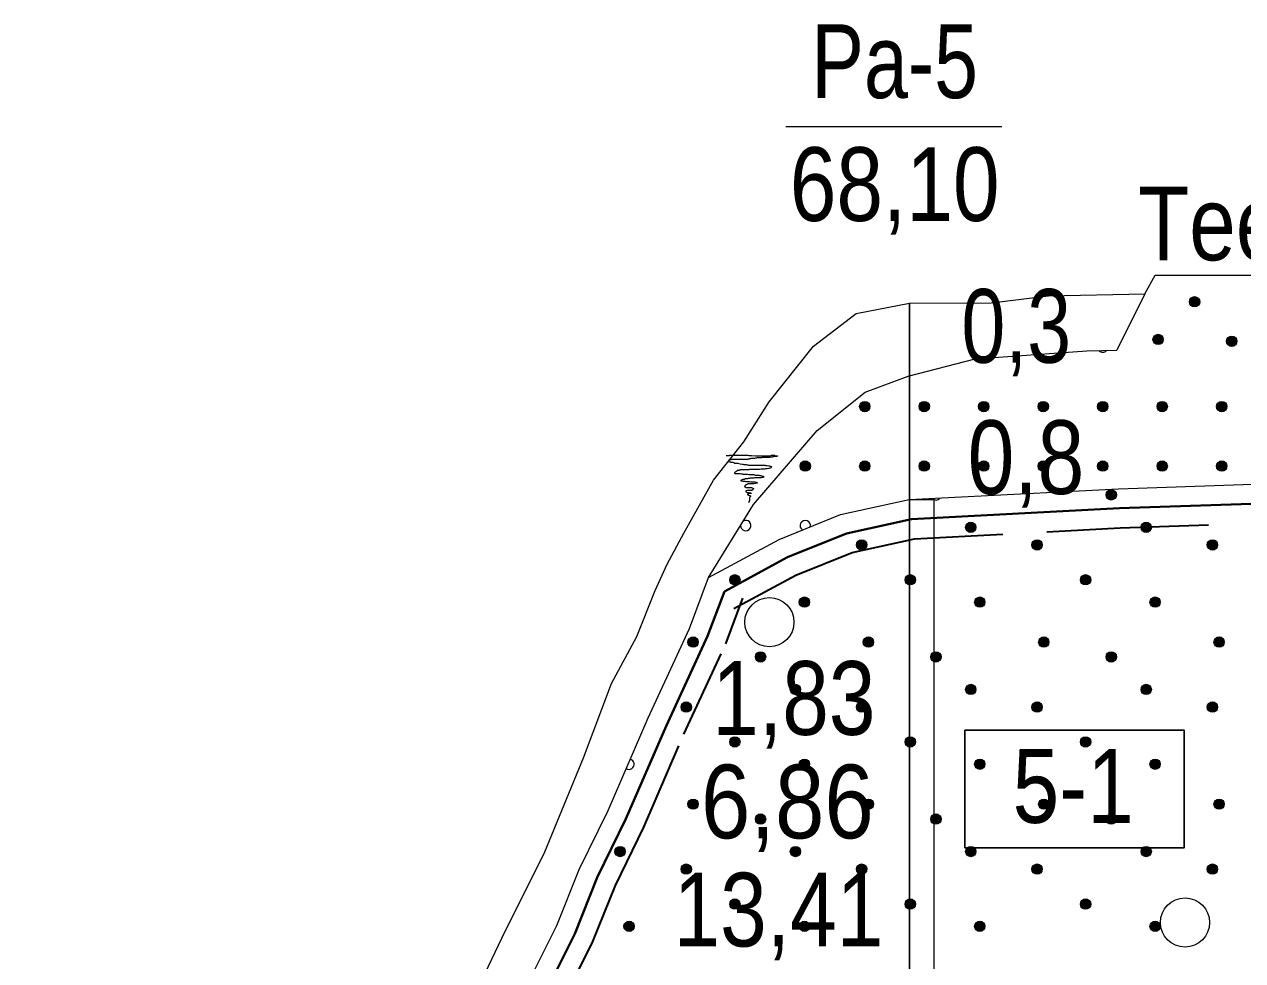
# Model space of a CAD drawing. Extents: x 640121 to 640955, y 6441885 to 6442246.
# Drawn here: x 640175.81 to 640225.36, y 6441992.66 to 6442030.76 of the extents above; entities that cross this region are included whole.
import ezdxf
from ezdxf.enums import TextEntityAlignment as Align

# ---------------------------------------------------------------- set-up
doc = ezdxf.new("R2010")
doc.units = 0
doc.header["$LTSCALE"] = 1.2
doc.linetypes.add('MEDIUM_DASHED', pattern=[4.5, 3, -1.5])
for name, color, linetype, lineweight in [('31', 7, 'Continuous', 13), ('32', 7, 'Continuous', 13), ('33', 7, 'Continuous', 13), ('35', 7, 'Continuous', 35), ('40', 7, 'Continuous', 13), ('44', 7, 'Continuous', 13), ('45', 7, 'Continuous', 13), ('47', 7, 'Continuous', 13)]:
    doc.layers.add(name, color=color, linetype=linetype, lineweight=lineweight)

msp = doc.modelspace()

# ---------------------------------------------------------------- hatches: boundary and pattern name
at = {"layer": '44'}
for points in [[(640220.231, 6442011.616, 1), (640219.811, 6442011.616, 1)], [(640214.517, 6442010.294, 1), (640214.097, 6442010.294, 1)], [(640221.65, 6442010.294, 1), (640221.23, 6442010.294, 1)], [(640210.077, 6442009.578, 1), (640209.657, 6442009.578, 1)], [(640217.21, 6442009.578, 1), (640216.79, 6442009.578, 1)], [(640224.343, 6442009.578, 1), (640223.923, 6442009.578, 1)], [(640204.921, 6442008.159, 1), (640204.501, 6442008.159, 1)], [(640212.054, 6442008.159, 1), (640211.634, 6442008.159, 1)], [(640219.187, 6442008.159, 1), (640218.767, 6442008.159, 1)], [(640207.748, 6442007.251, 1), (640207.328, 6442007.251, 1)], [(640214.881, 6442007.251, 1), (640214.461, 6442007.251, 1)], [(640222.014, 6442007.251, 1), (640221.594, 6442007.251, 1)], [(640203.218, 6442005.626, 1), (640202.798, 6442005.626, 1)], [(640210.351, 6442005.626, 1), (640209.931, 6442005.626, 1)], [(640217.484, 6442005.626, 1), (640217.064, 6442005.626, 1)], [(640224.617, 6442005.626, 1), (640224.197, 6442005.626, 1)], [(640205.965, 6442005.02, 1), (640205.545, 6442005.02, 1)], [(640213.098, 6442005.02, 1), (640212.678, 6442005.02, 1)], [(640220.231, 6442005.02, 1), (640219.811, 6442005.02, 1)], [(640207.384, 6442003.698, 1), (640206.964, 6442003.698, 1)], [(640214.517, 6442003.698, 1), (640214.097, 6442003.698, 1)], [(640221.65, 6442003.698, 1), (640221.23, 6442003.698, 1)], [(640202.944, 6442002.982, 1), (640202.524, 6442002.982, 1)], [(640210.077, 6442002.982, 1), (640209.657, 6442002.982, 1)], [(640217.21, 6442002.982, 1), (640216.79, 6442002.982, 1)], [(640224.343, 6442002.982, 1), (640223.923, 6442002.982, 1)], [(640204.921, 6442001.563, 1), (640204.501, 6442001.563, 1)], [(640212.054, 6442001.563, 1), (640211.634, 6442001.563, 1)], [(640219.187, 6442001.563, 1), (640218.767, 6442001.563, 1)], [(640207.748, 6442000.655, 1), (640207.328, 6442000.655, 1)], [(640214.881, 6442000.655, 1), (640214.461, 6442000.655, 1)], [(640222.014, 6442000.655, 1), (640221.594, 6442000.655, 1)], [(640203.218, 6441999.03, 1), (640202.798, 6441999.03, 1)], [(640210.351, 6441999.03, 1), (640209.931, 6441999.03, 1)], [(640217.484, 6441999.03, 1), (640217.064, 6441999.03, 1)], [(640224.617, 6441999.03, 1), (640224.197, 6441999.03, 1)], [(640205.965, 6441998.424, 1), (640205.545, 6441998.424, 1)], [(640213.098, 6441998.424, 1), (640212.678, 6441998.424, 1)], [(640220.231, 6441998.424, 1), (640219.811, 6441998.424, 1)], [(640200.251, 6441997.102, 1), (640199.831, 6441997.102, 1)], [(640207.384, 6441997.102, 1), (640206.964, 6441997.102, 1)], [(640214.517, 6441997.102, 1), (640214.097, 6441997.102, 1)], [(640221.65, 6441997.102, 1), (640221.23, 6441997.102, 1)], [(640202.944, 6441996.386, 1), (640202.524, 6441996.386, 1)], [(640210.077, 6441996.386, 1), (640209.657, 6441996.386, 1)], [(640217.21, 6441996.386, 1), (640216.79, 6441996.386, 1)], [(640224.343, 6441996.386, 1), (640223.923, 6441996.386, 1)], [(640204.921, 6441994.967, 1), (640204.501, 6441994.967, 1)], [(640212.054, 6441994.967, 1), (640211.634, 6441994.967, 1)], [(640219.187, 6441994.967, 1), (640218.767, 6441994.967, 1)], [(640200.615, 6441994.059, 1), (640200.195, 6441994.059, 1)], [(640207.748, 6441994.059, 1), (640207.328, 6441994.059, 1)], [(640214.881, 6441994.059, 1), (640214.461, 6441994.059, 1)], [(640222.014, 6441994.059, 1), (640221.594, 6441994.059, 1)]]:
    msp.add_hatch(color=256, dxfattribs=at).paths.add_polyline_path(points)
at = {"layer": '45'}
for points in [[(640223.621, 6442019.471, 1), (640223.201, 6442019.471, 1)], [(640222.136, 6442017.938, 1), (640221.716, 6442017.938, 1)], [(640225.13, 6442017.866, 1), (640224.71, 6442017.866, 1)], [(640210.203, 6442015.207, 1), (640209.783, 6442015.207, 1)], [(640212.623, 6442015.207, 1), (640212.203, 6442015.207, 1)], [(640215.043, 6442015.207, 1), (640214.623, 6442015.207, 1)], [(640217.463, 6442015.207, 1), (640217.043, 6442015.207, 1)], [(640219.883, 6442015.207, 1), (640219.463, 6442015.207, 1)], [(640222.303, 6442015.207, 1), (640221.883, 6442015.207, 1)], [(640224.723, 6442015.207, 1), (640224.303, 6442015.207, 1)], [(640207.783, 6442012.787, 1), (640207.363, 6442012.787, 1)], [(640210.203, 6442012.787, 1), (640209.783, 6442012.787, 1)], [(640212.623, 6442012.787, 1), (640212.203, 6442012.787, 1)], [(640215.043, 6442012.787, 1), (640214.623, 6442012.787, 1)], [(640217.463, 6442012.787, 1), (640217.043, 6442012.787, 1)], [(640219.883, 6442012.787, 1), (640219.463, 6442012.787, 1)], [(640222.303, 6442012.787, 1), (640221.883, 6442012.787, 1)], [(640224.723, 6442012.787, 1), (640224.303, 6442012.787, 1)]]:
    msp.add_hatch(color=256, dxfattribs=at).paths.add_polyline_path(points)

# ---------------------------------------------------------------- linework, layer by layer
at = {"layer": '31'}
msp.add_line((640221.38, 6442019.79), (640220.24, 6442017.5), dxfattribs=at)
for points in [[(640192.4, 6441987.63), (640195.23, 6441993.58), (640196.98, 6441997.09), (640198.55, 6442000.91), (640199.69, 6442003.94), (640200.72, 6442005.85), (640201.47, 6442007.72), (640201.96, 6442008.8), (640202.64, 6442010.06), (640203.84, 6442012.22), (640205.08, 6442013.77), (640206.11, 6442015.4), (640207.91, 6442017.67), (640209.64, 6442018.99), (640211.81, 6442019.41), (640215.13, 6442019.43), (640217.47, 6442019.72), (640221.38, 6442019.79), (640221.81, 6442020.56), (640225.76, 6442020.56)], [(640196.56, 6441992.27), (640197.47, 6441994.09), (640198.38, 6441996.37), (640199.55, 6441998.77), (640201.18, 6442002.54), (640202.86, 6442006.18), (640203.64, 6442008.25), (640205.47, 6442011.23), (640208.06, 6442014.23), (640210.01, 6442015.79), (640211.76, 6442016.44), (640214.49, 6442017.15), (640219.03, 6442017.48), (640220.24, 6442017.5)], [(640203.64, 6442008.25), (640206.51, 6442009.8), (640209.01, 6442010.81), (640211.8, 6442011.42), (640220.31, 6442011.86), (640226.94, 6442012.09), (640231.69, 6442012.26), (640234.41, 6442012.07), (640236.57, 6442011.92), (640240.41, 6442011.03), (640242.19, 6442010.47)]]:
    msp.add_lwpolyline(points, dxfattribs=at)
at = {"layer": '32'}
msp.add_line((640206.78, 6442026.6), (640215.57, 6442026.6), dxfattribs=at)
at = {"layer": '32', "lineweight": 25}
msp.add_line((640211.81, 6442019.41), (640211.81, 6441914.41), dxfattribs=at)
at = {"layer": '33'}
msp.add_lwpolyline([(640212.81, 6441989.41), (640212.81, 6442011.41), (640211.81, 6442011.41), (640211.81, 6441989.41)], close=True, dxfattribs=at)
at = {"layer": '33', "lineweight": 25}
msp.add_lwpolyline([(640214.07, 6442002.04), (640222.99, 6442002.04), (640222.99, 6441997.26), (640214.07, 6441997.26)], close=True, dxfattribs=at)
at = {"layer": '35', "lineweight": 40}
for points in [[(640204.29, 6442007.69), (640206.85, 6442009.08), (640209.25, 6442010.04), (640211.9, 6442010.62), (640220.35, 6442011.07), (640226.96, 6442011.29), (640231.68, 6442011.46), (640234.36, 6442011.28), (640236.45, 6442011.13), (640240.2, 6442010.26), (640241.6, 6442009.82)], [(640175.81, 6441965.88), (640176.44, 6441966.07), (640179.09, 6441967.84), (640182.86, 6441971.46), (640184.6, 6441973.14), (640186.28, 6441975.02), (640188.99, 6441978.04), (640192.07, 6441982.34), (640194.62, 6441986.76), (640196.44, 6441989.9), (640197.29, 6441991.94), (640198.2, 6441993.76), (640199.11, 6441996.04), (640200.28, 6441998.44), (640201.91, 6442002.21), (640203.6, 6442005.87), (640204.29, 6442007.69)]]:
    msp.add_lwpolyline(points, dxfattribs=at)
at = {"layer": '35', "linetype": 'MEDIUM_DASHED'}
for points in [[(640204.67, 6442006.99), (640207.19, 6442008.35), (640209.48, 6442009.27), (640212.01, 6442009.83), (640220.38, 6442010.27), (640226.99, 6442010.49), (640231.66, 6442010.66), (640234.3, 6442010.48), (640236.33, 6442010.33), (640239.99, 6442009.48), (640241.36, 6442009.06)], [(640176.61, 6441965.22), (640179.6, 6441967.21), (640183.42, 6441970.88), (640185.17, 6441972.59), (640186.87, 6441974.49), (640189.62, 6441977.53), (640192.74, 6441981.9), (640195.31, 6441986.36), (640197.15, 6441989.55), (640198.02, 6441991.61), (640198.93, 6441993.44), (640199.85, 6441995.72), (640201.01, 6441998.1), (640202.64, 6442001.88), (640204.34, 6442005.56), (640205.04, 6442007.41)]]:
    msp.add_lwpolyline(points, dxfattribs=at)
at = {"layer": '40'}
for points in [[(640204.35, 6442013.22), (640204.38, 6442013.22), (640204.43, 6442013.22), (640204.49, 6442013.22), (640204.5, 6442013.23), (640204.55, 6442013.23), (640204.63, 6442013.23), (640204.79, 6442013.23), (640204.88, 6442013.23), (640204.9, 6442013.23), (640204.92, 6442013.23), (640204.95, 6442013.23), (640205, 6442013.23), (640205.05, 6442013.23), (640205.09, 6442013.23), (640205.12, 6442013.23), (640205.16, 6442013.23), (640205.2, 6442013.23), (640205.24, 6442013.23), (640205.28, 6442013.22), (640205.3, 6442013.22), (640205.34, 6442013.22), (640205.39, 6442013.22), (640205.55, 6442013.21), (640205.71, 6442013.21), (640205.76, 6442013.21), (640205.79, 6442013.21), (640205.81, 6442013.21), (640205.83, 6442013.21), (640205.87, 6442013.21), (640205.91, 6442013.21), (640205.94, 6442013.21), (640205.96, 6442013.21), (640205.97, 6442013.21), (640205.99, 6442013.21), (640206.02, 6442013.21), (640206.04, 6442013.21), (640206.06, 6442013.21), (640206.11, 6442013.21), (640206.14, 6442013.21), (640206.18, 6442013.22), (640206.2, 6442013.23), (640206.23, 6442013.23), (640206.25, 6442013.23), (640206.27, 6442013.23), (640206.3, 6442013.23), (640206.32, 6442013.23), (640206.33, 6442013.22), (640206.36, 6442013.21), (640206.38, 6442013.21)], [(640205.12, 6442013.06), (640205.1, 6442013.05), (640205.07, 6442013.05), (640205.05, 6442013.05), (640205.03, 6442013.05), (640205.01, 6442013.05), (640204.99, 6442013.05), (640204.97, 6442013.05), (640204.94, 6442013.05), (640204.91, 6442013.05), (640204.89, 6442013.05), (640204.86, 6442013.05), (640204.84, 6442013.05), (640204.82, 6442013.05), (640204.8, 6442013.05), (640204.78, 6442013.05), (640204.76, 6442013.05), (640204.72, 6442013.05), (640204.7, 6442013.05), (640204.68, 6442013.05), (640204.65, 6442013.05), (640204.64, 6442013.05), (640204.61, 6442013.05), (640204.59, 6442013.05), (640204.57, 6442013.05), (640204.55, 6442013.05), (640204.53, 6442013.03), (640204.5, 6442013.03), (640204.49, 6442013.03), (640204.47, 6442013.02), (640204.46, 6442013.02), (640204.45, 6442013), (640204.44, 6442012.99), (640204.45, 6442012.97), (640204.5, 6442012.96), (640204.53, 6442012.96), (640204.55, 6442012.95), (640204.57, 6442012.95), (640204.59, 6442012.94), (640204.6, 6442012.94), (640204.63, 6442012.94), (640204.65, 6442012.93), (640204.67, 6442012.93), (640204.71, 6442012.91), (640204.74, 6442012.91), (640204.78, 6442012.91), (640204.8, 6442012.9), (640204.83, 6442012.9), (640204.87, 6442012.89), (640204.92, 6442012.88)], [(640206.38, 6442013.21), (640206.4, 6442013.21), (640206.42, 6442013.21), (640206.44, 6442013.21), (640206.45, 6442013.2), (640206.44, 6442013.19), (640206.45, 6442013.2), (640206.43, 6442013.19), (640206.41, 6442013.18), (640206.38, 6442013.18), (640206.36, 6442013.18), (640206.33, 6442013.18), (640206.32, 6442013.17), (640206.3, 6442013.17), (640206.29, 6442013.16), (640206.26, 6442013.16), (640206.22, 6442013.15), (640206.2, 6442013.15), (640206.14, 6442013.15), (640206.12, 6442013.14), (640206.1, 6442013.14), (640206.08, 6442013.14), (640206.05, 6442013.14), (640206.03, 6442013.14), (640206, 6442013.13), (640205.99, 6442013.13), (640205.93, 6442013.13), (640205.9, 6442013.13), (640205.87, 6442013.13), (640205.82, 6442013.13), (640205.79, 6442013.12), (640205.77, 6442013.12), (640205.74, 6442013.12), (640205.71, 6442013.12), (640205.63, 6442013.12), (640205.61, 6442013.12), (640205.59, 6442013.11), (640205.55, 6442013.11), (640205.51, 6442013.1), (640205.46, 6442013.09), (640205.43, 6442013.09), (640205.39, 6442013.09), (640205.36, 6442013.09), (640205.34, 6442013.08), (640205.31, 6442013.08), (640205.3, 6442013.07), (640205.28, 6442013.07), (640205.25, 6442013.07), (640205.22, 6442013.06), (640205.21, 6442013.06), (640205.14, 6442013.06), (640205.12, 6442013.06)], [(640205.53, 6442012.65), (640205.49, 6442012.65), (640205.45, 6442012.65), (640205.41, 6442012.65), (640205.38, 6442012.65), (640205.35, 6442012.65), (640205.31, 6442012.65), (640205.27, 6442012.64), (640205.18, 6442012.64), (640205.13, 6442012.64), (640205.11, 6442012.64), (640205.07, 6442012.64), (640205.01, 6442012.63), (640204.94, 6442012.63), (640204.92, 6442012.62), (640204.89, 6442012.62), (640204.88, 6442012.61), (640204.86, 6442012.61), (640204.84, 6442012.61), (640204.82, 6442012.6), (640204.8, 6442012.6), (640204.79, 6442012.58), (640204.76, 6442012.57), (640204.74, 6442012.55), (640204.74, 6442012.54), (640204.72, 6442012.54), (640204.71, 6442012.52), (640204.7, 6442012.51), (640204.7, 6442012.5), (640204.71, 6442012.49), (640204.73, 6442012.49), (640204.76, 6442012.49), (640204.78, 6442012.49), (640204.83, 6442012.49), (640204.88, 6442012.48), (640204.92, 6442012.48), (640204.98, 6442012.47), (640205.01, 6442012.47), (640205.04, 6442012.46), (640205.07, 6442012.46), (640205.16, 6442012.46), (640205.22, 6442012.46), (640205.28, 6442012.45), (640205.33, 6442012.45), (640205.4, 6442012.44), (640205.48, 6442012.44), (640205.54, 6442012.42), (640205.58, 6442012.42), (640205.63, 6442012.42), (640205.67, 6442012.42)], [(640204.92, 6442012.88), (640205, 6442012.87), (640205.04, 6442012.86), (640205.07, 6442012.85), (640205.12, 6442012.85), (640205.17, 6442012.85), (640205.21, 6442012.84), (640205.24, 6442012.84), (640205.26, 6442012.83), (640205.3, 6442012.83), (640205.33, 6442012.83), (640205.37, 6442012.82), (640205.42, 6442012.82), (640205.45, 6442012.82), (640205.5, 6442012.82), (640205.54, 6442012.82), (640205.57, 6442012.82), (640205.59, 6442012.82), (640205.63, 6442012.82), (640205.66, 6442012.82), (640205.7, 6442012.82), (640205.75, 6442012.82), (640205.79, 6442012.82), (640205.82, 6442012.82), (640205.87, 6442012.82), (640205.88, 6442012.82), (640205.91, 6442012.82), (640205.94, 6442012.82), (640205.97, 6442012.81), (640206, 6442012.81), (640206.03, 6442012.81), (640206.09, 6442012.8), (640206.12, 6442012.79), (640206.15, 6442012.78), (640206.18, 6442012.77), (640206.2, 6442012.76), (640206.2, 6442012.75), (640206.19, 6442012.73), (640206.18, 6442012.72), (640206.17, 6442012.72), (640206.15, 6442012.7), (640206.13, 6442012.7), (640206.09, 6442012.69), (640206.02, 6442012.68), (640205.95, 6442012.67), (640205.91, 6442012.66), (640205.87, 6442012.66), (640205.82, 6442012.66), (640205.78, 6442012.66), (640205.71, 6442012.65), (640205.61, 6442012.65), (640205.53, 6442012.65)], [(640205.67, 6442012.42), (640205.69, 6442012.42), (640205.72, 6442012.41), (640205.76, 6442012.4), (640205.79, 6442012.39), (640205.82, 6442012.38), (640205.84, 6442012.37), (640205.87, 6442012.37), (640205.88, 6442012.36), (640205.89, 6442012.34), (640205.88, 6442012.33), (640205.87, 6442012.33), (640205.85, 6442012.32), (640205.79, 6442012.31), (640205.76, 6442012.31), (640205.74, 6442012.31), (640205.7, 6442012.31), (640205.66, 6442012.31), (640205.62, 6442012.31), (640205.6, 6442012.31), (640205.57, 6442012.31), (640205.51, 6442012.31), (640205.47, 6442012.3), (640205.45, 6442012.3), (640205.42, 6442012.3), (640205.4, 6442012.29), (640205.37, 6442012.29), (640205.33, 6442012.29), (640205.3, 6442012.28), (640205.25, 6442012.28), (640205.22, 6442012.27), (640205.21, 6442012.27), (640205.18, 6442012.27), (640205.16, 6442012.27), (640205.13, 6442012.27), (640205.13, 6442012.25), (640205.1, 6442012.25), (640205.09, 6442012.24), (640205.07, 6442012.24), (640205.04, 6442012.24), (640205.01, 6442012.23), (640204.98, 6442012.22), (640204.96, 6442012.21), (640204.95, 6442012.2), (640204.95, 6442012.18), (640204.97, 6442012.18), (640205, 6442012.18), (640205.05, 6442012.17), (640205.09, 6442012.17), (640205.12, 6442012.17), (640205.16, 6442012.16), (640205.19, 6442012.16)], [(640205.19, 6442012.16), (640205.21, 6442012.16), (640205.22, 6442012.16), (640205.25, 6442012.16), (640205.29, 6442012.16), (640205.31, 6442012.16), (640205.36, 6442012.15), (640205.4, 6442012.15), (640205.42, 6442012.15), (640205.45, 6442012.15), (640205.46, 6442012.15), (640205.49, 6442012.15), (640205.52, 6442012.15), (640205.55, 6442012.13), (640205.57, 6442012.13), (640205.6, 6442012.12), (640205.61, 6442012.12), (640205.61, 6442012.09), (640205.55, 6442012.08), (640205.48, 6442012.07), (640205.45, 6442012.07), (640205.39, 6442012.07), (640205.36, 6442012.07), (640205.33, 6442012.07), (640205.29, 6442012.06), (640205.25, 6442012.06), (640205.22, 6442012.05), (640205.18, 6442012.03), (640205.16, 6442012.02), (640205.14, 6442012.01), (640205.13, 6442012), (640205.12, 6442011.98), (640205.11, 6442011.97), (640205.1, 6442011.95), (640205.11, 6442011.94), (640205.13, 6442011.94), (640205.17, 6442011.92), (640205.24, 6442011.92), (640205.29, 6442011.92), (640205.32, 6442011.91), (640205.34, 6442011.91), (640205.38, 6442011.91), (640205.42, 6442011.9), (640205.47, 6442011.88), (640205.47, 6442011.86), (640205.46, 6442011.84), (640205.46, 6442011.83), (640205.42, 6442011.8), (640205.4, 6442011.79), (640205.37, 6442011.79), (640205.33, 6442011.79), (640205.29, 6442011.79), (640205.25, 6442011.79), (640205.21, 6442011.79), (640205.17, 6442011.78), (640205.16, 6442011.76), (640205.16, 6442011.75), (640205.16, 6442011.74), (640205.18, 6442011.73), (640205.24, 6442011.71), (640205.28, 6442011.71), (640205.31, 6442011.7), (640205.34, 6442011.7), (640205.37, 6442011.69), (640205.39, 6442011.68), (640205.37, 6442011.67), (640205.34, 6442011.67), (640205.31, 6442011.67), (640205.26, 6442011.66), (640205.24, 6442011.66), (640205.22, 6442011.65), (640205.22, 6442011.63), (640205.24, 6442011.62), (640205.25, 6442011.61), (640205.27, 6442011.6), (640205.29, 6442011.59), (640205.32, 6442011.59), (640205.34, 6442011.58), (640205.35, 6442011.56), (640205.34, 6442011.55), (640205.33, 6442011.53), (640205.32, 6442011.51), (640205.31, 6442011.5), (640205.31, 6442011.47), (640205.31, 6442011.45), (640205.31, 6442011.43), (640205.3, 6442011.41), (640205.3, 6442011.39), (640205.3, 6442011.38), (640205.29, 6442011.35), (640205.28, 6442011.34), (640205.28, 6442011.31), (640205.28, 6442011.31), (640205.28, 6442011.32)]]:
    msp.add_lwpolyline(points, dxfattribs=at)
at = {"layer": '44'}
for centre in [(640220.021, 6442011.616), (640214.307, 6442010.294), (640221.44, 6442010.294), (640209.867, 6442009.578), (640217, 6442009.578), (640224.133, 6442009.578), (640204.711, 6442008.159), (640211.844, 6442008.159), (640218.977, 6442008.159), (640207.538, 6442007.251), (640214.671, 6442007.251), (640221.804, 6442007.251), (640203.008, 6442005.626), (640210.141, 6442005.626), (640217.274, 6442005.626), (640224.407, 6442005.626), (640205.755, 6442005.02), (640212.888, 6442005.02), (640220.021, 6442005.02), (640207.174, 6442003.698), (640214.307, 6442003.698), (640221.44, 6442003.698), (640202.734, 6442002.982), (640209.867, 6442002.982), (640217, 6442002.982), (640224.133, 6442002.982), (640204.711, 6442001.563), (640211.844, 6442001.563), (640218.977, 6442001.563), (640207.538, 6442000.655), (640214.671, 6442000.655), (640221.804, 6442000.655), (640203.008, 6441999.03), (640210.141, 6441999.03), (640217.274, 6441999.03), (640224.407, 6441999.03), (640205.755, 6441998.424), (640212.888, 6441998.424), (640220.021, 6441998.424), (640200.041, 6441997.102), (640207.174, 6441997.102), (640214.307, 6441997.102), (640221.44, 6441997.102), (640202.734, 6441996.386), (640209.867, 6441996.386), (640217, 6441996.386), (640224.133, 6441996.386), (640204.711, 6441994.967), (640211.844, 6441994.967), (640218.977, 6441994.967), (640200.405, 6441994.059), (640207.538, 6441994.059), (640214.671, 6441994.059), (640221.804, 6441994.059)]:
    msp.add_circle(centre, 0.21, dxfattribs=at)
for centre, start, end in [((640212.888, 6442011.616), 224.5244, 321.4618), ((640207.174, 6442010.294), 280.5821, 303.0207), ((640200.405, 6442000.655), 236.2769, 77.0877)]:
    msp.add_arc(centre, 0.21, start, end, dxfattribs=at)
at = {"layer": '45'}
for centre in [(640223.411, 6442019.471), (640221.926, 6442017.938), (640224.92, 6442017.866), (640209.993, 6442015.207), (640212.413, 6442015.207), (640214.833, 6442015.207), (640217.253, 6442015.207), (640219.673, 6442015.207), (640222.093, 6442015.207), (640224.513, 6442015.207), (640207.573, 6442012.787), (640209.993, 6442012.787), (640212.413, 6442012.787), (640214.833, 6442012.787), (640217.253, 6442012.787), (640219.673, 6442012.787), (640222.093, 6442012.787), (640224.513, 6442012.787)]:
    msp.add_circle(centre, 0.21, dxfattribs=at)
for centre, start, end in [((640219.673, 6442017.627), 222.8026, 318.937), ((640205.153, 6442010.367), 177.8236, 119.2155), ((640207.573, 6442010.367), 344.901, 238.7018)]:
    msp.add_arc(centre, 0.21, start, end, dxfattribs=at)
at = {"layer": '47'}
for centre in [(640206.114, 6442006.437), (640223.019, 6441994.213)]:
    msp.add_circle(centre, 1, dxfattribs=at)

# ---------------------------------------------------------------- texts
at = {"layer": '31', "width": 0.85}
msp.add_text('Tee', height=3, dxfattribs=at).set_placement((640224.045, 6442021.16), align=Align.CENTER)
at = {"layer": '32'}
for s, width, p in [('Pa-5', 0.8, (640211.21, 6442027.76)), ('68,10', 0.85, (640211.21, 6442022.76)), ('0,3', 0.8, (640216.155, 6442016.99)), ('0,8', 0.85, (640216.55, 6442011.65)), ('1,83', 0.85, (640207.11, 6442001.85)), ('6,86', 0.9, (640206.845, 6441997.64)), ('13,41', 0.85, (640206.48, 6441993.24))]:
    msp.add_text(s, height=3, dxfattribs=dict(at, width=width)).set_placement(p, align=Align.CENTER)
at = {"layer": '33', "width": 0.85}
msp.add_text('5-1', height=3, dxfattribs=at).set_placement((640218.47, 6441998.27), align=Align.CENTER)

doc.saveas('drawing.dxf')
